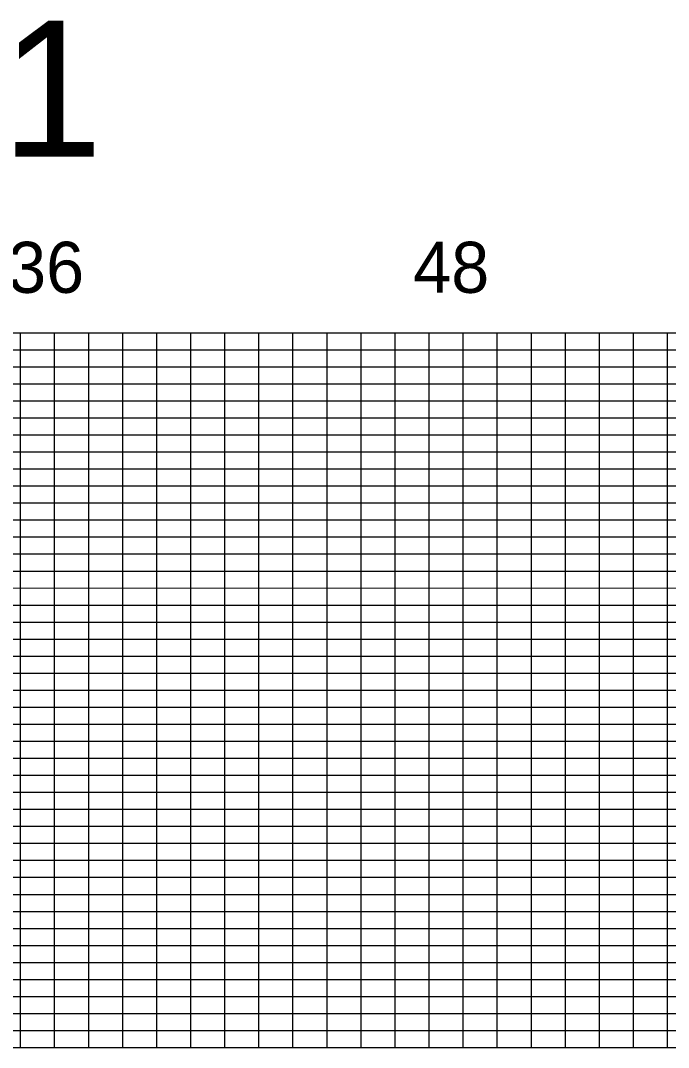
# Model space of a CAD drawing. Extents: x 1950433 to 1956806, y 750939 to 777666.
# Drawn here: x 1953090 to 1954041, y 750964 to 752473 of the extents above; entities that cross this region are included whole.
import ezdxf

# ---------------------------------------------------------------- set-up
doc = ezdxf.new("R2010")
doc.units = 0
doc.layers.add('RD_PD_WallFill', color=7, linetype='Continuous')
doc.layers.add('RD_Sketch8', color=7, linetype='Continuous')

msp = doc.modelspace()

# ---------------------------------------------------------------- linework, layer by layer
at = {"layer": 'RD_PD_WallFill'}
for p, q in [((1951339.9, 752014.1), (1956689.9, 752014.1)), ((1953089.9, 750964.1), (1953089.9, 752014.1)), ((1953139.9, 750964.1), (1953139.9, 752014.1)), ((1953189.9, 750964.1), (1953189.9, 752014.1)), ((1953239.9, 750964.1), (1953239.9, 752014.1)), ((1953289.9, 750964.1), (1953289.9, 752014.1)), ((1953339.9, 750964.1), (1953339.9, 752014.1)), ((1953389.9, 750964.1), (1953389.9, 752014.1)), ((1953439.9, 750964.1), (1953439.9, 752014.1)), ((1953489.9, 750964.1), (1953489.9, 752014.1)), ((1953539.9, 750964.1), (1953539.9, 752014.1)), ((1953589.9, 750964.1), (1953589.9, 752014.1)), ((1953639.9, 750964.1), (1953639.9, 752014.1)), ((1953689.9, 750964.1), (1953689.9, 752014.1)), ((1953739.9, 750964.1), (1953739.9, 752014.1)), ((1953789.9, 750964.1), (1953789.9, 752014.1)), ((1953839.9, 750964.1), (1953839.9, 752014.1)), ((1953889.9, 750964.1), (1953889.9, 752014.1)), ((1953939.9, 750964.1), (1953939.9, 752014.1)), ((1953989.9, 750964.1), (1953989.9, 752014.1)), ((1954039.9, 750964.1), (1954039.9, 752014.1)), ((1951789.9, 751989.1), (1956689.9, 751989.1)), ((1951789.9, 751964.1), (1956689.9, 751964.1)), ((1951789.9, 751939.1), (1956689.9, 751939.1)), ((1951789.9, 751914.2), (1956689.9, 751914.1)), ((1951789.9, 751889.1), (1956689.9, 751889.2)), ((1951339.9, 751864.1), (1956689.9, 751864.1)), ((1951339.9, 751839.1), (1956689.9, 751839.1)), ((1951339.9, 751814.1), (1956689.9, 751814.2)), ((1951339.9, 751789.2), (1956689.9, 751789.1)), ((1951339.9, 751764.2), (1956689.9, 751764.2)), ((1951339.9, 751739.1), (1956689.9, 751739.1)), ((1951339.9, 751714.1), (1956689.9, 751714.1)), ((1951339.9, 751689.2), (1956689.9, 751689.1)), ((1951339.9, 751664.1), (1956689.9, 751664.1)), ((1951339.9, 751639.2), (1956689.9, 751639.1)), ((1951339.9, 751614.1), (1956689.9, 751614.1)), ((1951339.9, 751589.1), (1956689.9, 751589.2)), ((1951339.9, 751564.1), (1956689.9, 751564.1)), ((1951339.9, 751539.1), (1956689.9, 751539.2)), ((1951339.9, 751514.1), (1956689.9, 751514.1)), ((1951339.9, 751489.1), (1956689.9, 751489.1)), ((1951339.9, 751464.2), (1956689.9, 751464.1)), ((1951339.9, 751439.1), (1956689.9, 751439.1)), ((1951339.9, 751414.1), (1956689.9, 751414.1)), ((1951339.9, 751389.1), (1956689.9, 751389.1)), ((1951339.9, 751364.1), (1956689.9, 751364.2)), ((1951339.9, 751339.1), (1956689.9, 751339.1)), ((1951339.9, 751314.1), (1956689.9, 751314.1)), ((1951339.9, 751289.1), (1956689.9, 751289.1)), ((1951339.9, 751264.1), (1956689.9, 751264.1)), ((1951339.9, 751239.1), (1956689.9, 751239.1)), ((1951339.9, 751214.1), (1956689.9, 751214.1)), ((1951339.9, 751189.1), (1956689.9, 751189.1)), ((1951339.9, 751164.1), (1956689.9, 751164.1)), ((1951339.9, 751139.1), (1956689.9, 751139.1)), ((1951339.9, 751114.1), (1956689.9, 751114.1)), ((1951339.9, 751089.1), (1956689.9, 751089.1)), ((1951339.9, 751064.1), (1956689.9, 751064.1)), ((1951339.9, 751039.1), (1956689.9, 751039.1)), ((1951339.9, 751014.1), (1956689.9, 751014.1)), ((1951389.9, 750989.1), (1956689.9, 750989.1)), ((1951339.9, 750964.1), (1956689.9, 750964.1))]:
    msp.add_line(p, q, dxfattribs=at)

# ---------------------------------------------------------------- texts
for s, p in [('22x36', (1952909.9, 752072.8)), ('48', (1953666.5, 752072.8))]:
    msp.add_text(s, height=75, dxfattribs=at).set_placement(p)
at = {"layer": 'RD_Sketch8'}
msp.add_text('11', height=200, dxfattribs=at).set_placement((1952912.9, 752272.8))

doc.saveas('drawing.dxf')
